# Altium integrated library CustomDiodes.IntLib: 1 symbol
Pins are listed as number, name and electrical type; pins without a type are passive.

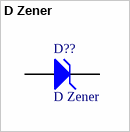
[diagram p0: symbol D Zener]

## D Zener
designator D??
Zener Diode
footprint Zener Diode (Zener Diode 13.8)
pins: 1 A, 2 K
